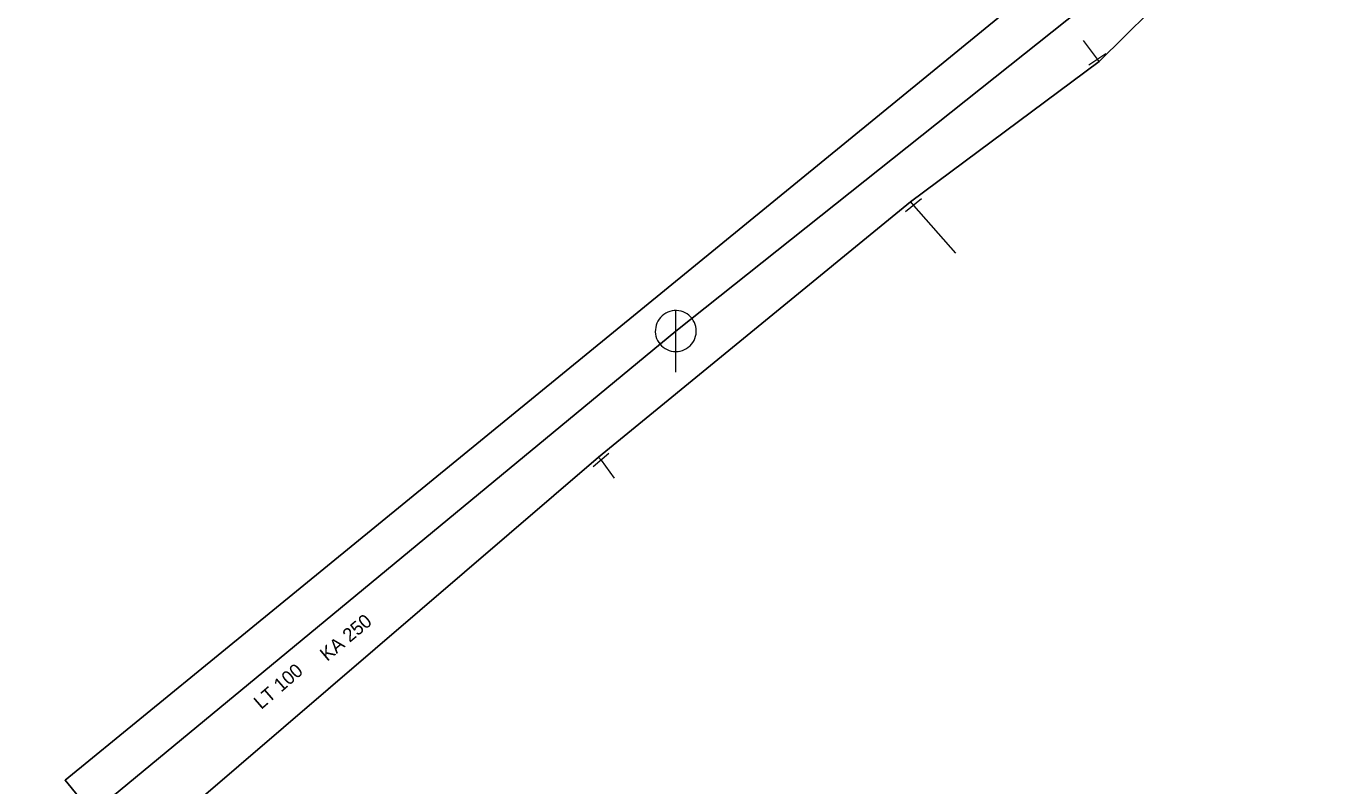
# Model space of a CAD drawing. Extents: x -688296 to -687852, y -973332 to -972816.
# Drawn here: x -688205.5 to -688141.5, y -973132.5 to -973095.5 of the extents above; entities that cross this region are included whole.
import ezdxf
from ezdxf.enums import TextEntityAlignment as Align

# ---------------------------------------------------------------- set-up
doc = ezdxf.new("R2010")
doc.units = 0
doc.header["$LTSCALE"] = 0.27
for name, color, linetype, lineweight in [('1', 7, 'Continuous', 25), ('13', 7, 'Continuous', 13), ('14', 7, 'Continuous', 13), ('17', 7, 'Continuous', 25), ('22', 7, 'Continuous', 13), ('34', 7, 'Continuous', 13)]:
    doc.layers.add(name, color=color, linetype=linetype, lineweight=lineweight)

msp = doc.modelspace()

# ---------------------------------------------------------------- linework, layer by layer
at = {"layer": '13'}
for p, q in [((-688153.3, -973097.079), (-688153.98, -973096.17)), ((-688162.27, -973104.219), (-688160.219, -973106.559)), ((-688177.51, -973116.649), (-688176.87, -973117.53))]:
    msp.add_line(p, q, dxfattribs=at)
at = {"layer": '14', "lineweight": 25}
for p, q in [((-688173.864, -973110.353), (-688141.707, -973084.764)), ((-688205.548, -973136.536), (-688173.864, -973110.353))]:
    msp.add_line(p, q, dxfattribs=at)
at = {"layer": '14'}
for p, q in [((-688153.219, -973097.199), (-688153.3, -973097.079)), ((-688162.42, -973104.039), (-688162.27, -973104.219)), ((-688177.64, -973116.5), (-688177.51, -973116.649))]:
    msp.add_line(p, q, dxfattribs=at)
at = {"layer": '17'}
for points in [[(-688123.609, -972815.609), (-688135.91, -972839.761), (-688146.524, -972867.704), (-688149.164, -972878.87), (-688150.368, -972974.473), (-688134.778, -973051.136), (-688125.903, -973068.701), (-688203.651, -973132.27), (-688148.612, -973199.748), (-688078.631, -973291.807), (-688049.631, -973331.642)], [(-688204.44, -973139.53), (-688204.19, -973139.309), (-688203.89, -973139.05), (-688177.64, -973116.5), (-688162.42, -973104.039), (-688153.219, -973097.199), (-688149.52, -973093.53), (-688143.109, -973089.09)]]:
    msp.add_lwpolyline(points, dxfattribs=at)
at = {"layer": '22'}
msp.add_line((-688173.864, -973112.353), (-688173.863, -973109.353), dxfattribs=at)
msp.add_lwpolyline([(-688172.864, -973110.353), (-688172.869, -973110.244), (-688172.887, -973110.136), (-688172.917, -973110.03), (-688172.957, -973109.929), (-688173.009, -973109.832), (-688173.071, -973109.742), (-688173.143, -973109.659), (-688173.223, -973109.585), (-688173.311, -973109.519), (-688173.405, -973109.464), (-688173.505, -973109.419), (-688173.61, -973109.386), (-688173.717, -973109.364), (-688173.826, -973109.354), (-688173.936, -973109.356), (-688174.044, -973109.37), (-688174.151, -973109.395), (-688174.254, -973109.432), (-688174.352, -973109.481), (-688174.444, -973109.539), (-688174.53, -973109.608), (-688174.607, -973109.685), (-688174.676, -973109.771), (-688174.735, -973109.863), (-688174.783, -973109.961), (-688174.82, -973110.064), (-688174.846, -973110.171), (-688174.86, -973110.279), (-688174.863, -973110.389), (-688174.853, -973110.498), (-688174.832, -973110.605), (-688174.798, -973110.709), (-688174.754, -973110.809), (-688174.699, -973110.904), (-688174.633, -973110.992), (-688174.559, -973111.072), (-688174.476, -973111.144), (-688174.386, -973111.206), (-688174.29, -973111.258), (-688174.188, -973111.299), (-688174.083, -973111.329), (-688173.975, -973111.347), (-688173.865, -973111.353), (-688173.756, -973111.347), (-688173.648, -973111.329), (-688173.543, -973111.3), (-688173.441, -973111.259), (-688173.344, -973111.207), (-688173.254, -973111.145), (-688173.171, -973111.074), (-688173.096, -973110.994), (-688173.031, -973110.906), (-688172.975, -973110.812), (-688172.931, -973110.712), (-688172.897, -973110.608), (-688172.875, -973110.5), (-688172.865, -973110.391)], close=True, dxfattribs=at)
at = {"layer": '34'}
for p, q in [((-688153.715, -973097.356), (-688152.883, -973096.802)), ((-688161.886, -973103.898), (-688162.654, -973104.538)), ((-688177.132, -973116.321), (-688177.888, -973116.976))]:
    msp.add_line(p, q, dxfattribs=at)

# ---------------------------------------------------------------- texts
at = {"layer": '1'}
for s, rotation, p in [('KA 250', 40, (-688189.7505, -973125.5589)), ('KA 250', 40, (-688189.7505, -973125.5589)), ('KA 250', 40, (-688189.7505, -973125.5589)), ('KA 250', 40, (-688189.7505, -973125.5589)), ('KA 250', 40, (-688189.7505, -973125.5589)), ('LT 100', 41, (-688193.04, -973127.9372)), ('LT 100', 41, (-688193.04, -973127.9372)), ('LT 100', 41, (-688193.04, -973127.9372)), ('LT 100', 41, (-688193.04, -973127.9372)), ('LT 100', 41, (-688193.04, -973127.9372))]:
    msp.add_text(s, height=0.6667, rotation=rotation, dxfattribs=at).set_placement(p, align=Align.CENTER)

doc.saveas('drawing.dxf')
